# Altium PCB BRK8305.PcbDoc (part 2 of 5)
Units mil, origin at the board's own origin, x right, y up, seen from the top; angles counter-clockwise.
Board outline 5944.89 x 4139.76 mil, 4 copper layers (L1-Top, L2-GND, L3-GND, L4-BOT), stack 61.2 mil thick; 237 components, 286 nets, 1257 pads, 698 vias.
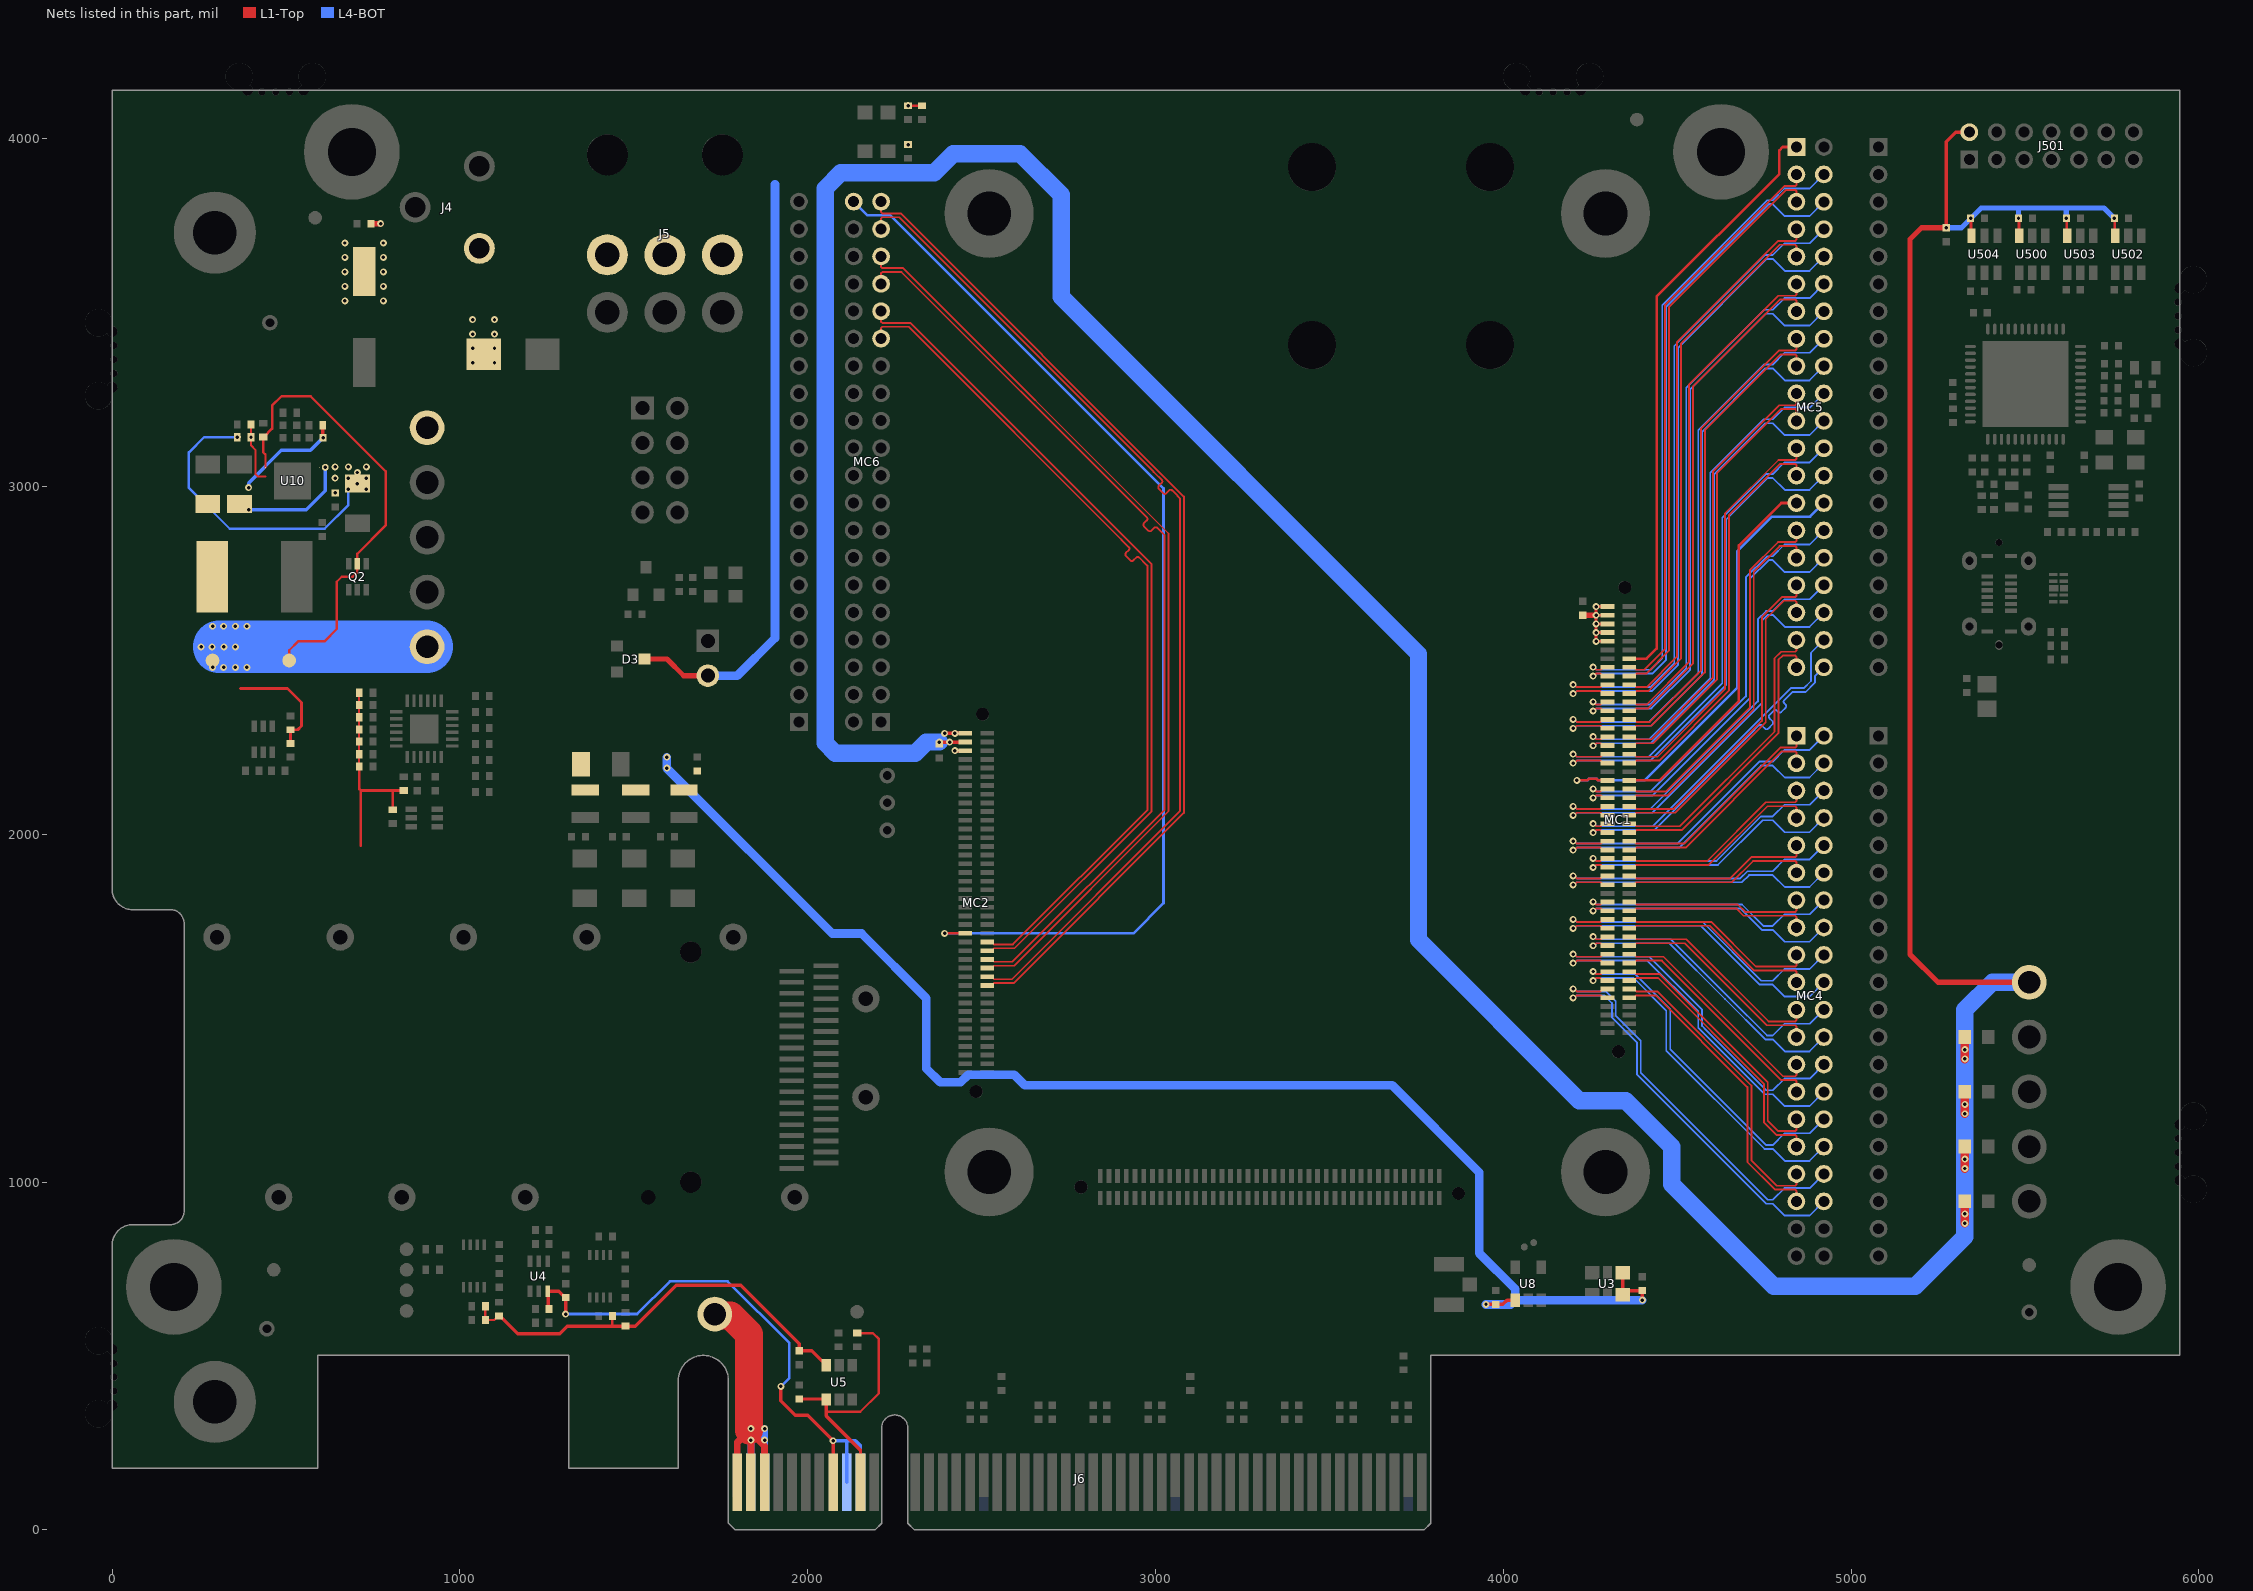
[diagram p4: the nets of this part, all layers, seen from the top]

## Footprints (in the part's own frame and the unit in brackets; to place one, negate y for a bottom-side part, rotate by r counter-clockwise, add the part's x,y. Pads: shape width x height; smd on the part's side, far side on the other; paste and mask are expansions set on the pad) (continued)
QSFP28_SINGLE_CAGE [mm]
  round 2 hole 1.05: 0(-1.1,3.1) 0(-1.1,-7.6) 0(-1.1,-16.6) 0(-1.1,-25.6) 0(-1.1,-34.6) 0(3.4,12.79) 0(10.6,12.79) 0(17.9,7.6) 0(17.9,-21.1) 0(17.9,-12.1) 0(17.9,-30.1)
  round 0 hole 1.05 unplated: 0(17.9,-3.1)
  L1-Top keep-out region: -2.7,13.5 -2.7,-37 19.5,-37 19.5,13.5 16.5,13.5 16.5,11.1 18,11.1 18,-1.6 15.9,-1.6 15.9,-3.5 0.9,-3.5 0.9,-1.6 -1.2,-1.6 -1.2,11.1 0.3,11.1 0.3,13.5
  silkscreen extent -1.1,-36.56 17.9,12.9, body extent -2,-48 18.81,12.91, height 10.41
RESC1005X06A [mm] "Chip Resistor, 2-Leads, Body 1.00x0.50mm, OK custom footprint"
  rect 0.5x0.6 smd mask+0.051: 1(-0.5,0) 2(0.5,0)
  body extent -0.52,-0.3 0.52,0.3, height 0.34
RESC1608N [mm] "Chip Resistor, Body 1.6x0.8mm, IPC Medium Density"
  rect 0.9x1 smd: 1(-0.85,0) 2(0.85,0)
  silkscreen extent -0.77,-0.68 0.78,0.68, body extent -0.84,-0.42 0.8,0.43, height 0.45
RESC2012N [mm] "Chip Resistor, Body 2.0x1.3mm, IPC Medium Density"
  rect 1.2x1.4 smd: 1(-0.9,0) 2(0.9,0)
  silkscreen extent -0.85,-0.89 0.85,0.88, body extent -1.07,-0.7 1.07,0.7, height 0.65
SIT9120AX-XB [mm]
  rect 1.05x1 smd: 1(-1.125,-0.8) 3(1.125,-0.8) 4(1.125,0.8) 6(-1.125,0.8)
  rect 0.65x1 smd: 2(0,-0.8) 5(0,0.8)
  silkscreen extent -1.85,-1.5 1.85,1.2
SOT23-5 [mm] "SOT-23; 5 Leads; Body 2.9 x 2.5 mm, inc. leads (LxW max)"
  rect 0.7x1 smd: 1(-0.95,-1.2) 2(0,-1.2) 3(0.95,-1.2) 4(0.95,1.2) 5(-0.95,1.2)
  silkscreen extent -1.5,-1.7 1.5,0.75
SOT23-6 [mm] "SOT-23; 6 Leads; Body 3.05 x 1.75 mm, inc. leads (LxW max)"
  rect 0.6x1.05 smd: 1(-0.95,-1.35) 2(0,-1.35) 3(0.95,-1.35) 4(0.95,1.35) 5(0,1.35) 6(-0.95,1.35)
  silkscreen extent -1.5,-1.9 1.5,0.75
SOT23-95P240X110 [mm] "SOT-23; 3 Leads; Body 3.0 x 2.6 mm, inc. leads (LxW max)"
  rect 0.8x0.9 smd: 1(-0.95,-1) 2(0.95,-1) 3(0,1)
  silkscreen extent -1.53,-1.45 1.54,0.77
SOT363-6N [mm] "SOT363, 6-Leads, Body 2x1.3mm, Pitch 0.65mm, Lead Span 2.1mm, IPC Medium Density"
  rect 0.85x0.4 smd: 1(-0.95,0.65) 2(-0.95,0) 3(-0.95,-0.65) 4(0.95,-0.65) 5(0.95,0) 6(0.95,0.65)
  silkscreen extent -1.37,-1.09 0.63,1.09, body extent -0.63,-1 0.63,1, height 1
Switch-PCB-wMounts [mm]
  round 3.5 hole 3.5 unplated paste-2539.97 mask+0.02: 0(-6.5,6.5) 0(-6.5,-6.5) 0(6.5,6.5) 0(6.5,-6.5)
  round 4.5 on Top Solder: 0(0,0)
  round 0.025 smd paste-1 mask-1: 1(-2.1,0) 2(2.1,0.001)
  L1-Top region: -0.672,-1.601 -0.664,-1.639 -0.642,-1.672 -0.61,-1.693 -0.572,-1.701 -0.572,-1.701 1.016,-1.701 0.657,-1.871 0.271,-1.967 0.271,-1.967 0.214,-1.982 0.17,-2.022 0.15,-2.077 0.159,-2.136 0.193,-2.183 0.246,-2.209 0.305,-2.208 0.305,-2.208 1.28,-1.829 1.97,-1.043 2.219,-0.027 2.219,-0.027 1.993,1.009 1.306,1.817 0.32,2.206 0.32,2.206 0.262,2.208 0.21,2.184 0.174,2.139 0.163,2.082 0.178,2.026 0.217,1.984 0.271,1.963 0.271,1.963 0.659,1.87 1.021,1.7 1.021,1.7 -0.6,1.7 -0.643,1.69 -0.678,1.662 -0.697,1.622 -0.697,1.578 -0.678,1.538 -0.643,1.51 -0.6,1.5 -0.6,1.5 1.297,1.5 1.561,1.222 1.767,0.899 1.767,0.899 -1.372,0.899 -1.415,0.889 -1.45,0.861 -1.469,0.821 -1.469,0.777 -1.45,0.737 -1.415,0.709 -1.372,0.699 -1.372,0.699 1.855,0.699 1.94,0.404 1.978,0.099 1.978,0.099 -1.572,0.099 -1.615,0.089 -1.65,0.061 -1.669,0.021 -1.669,-0.023 -1.65,-0.063 -1.615,-0.091 -1.572,-0.101 -1.572,-0.101 1.977,-0.101 1.937,-0.406 1.85,-0.701 1.85,-0.701 -1.472,-0.701 -1.515,-0.711 -1.55,-0.739 -1.569,-0.779 -1.569,-0.823 -1.55,-0.863 -1.515,-0.891 -1.472,-0.901 -1.472,-0.901 1.761,-0.901 1.555,-1.224 1.291,-1.501 1.291,-1.501 -0.572,-1.501 -0.61,-1.509 -0.642,-1.53 -0.664,-1.563 -0.672,-1.601
  L1-Top region: 1.213,-1.295 1.256,-1.285 1.291,-1.257 1.31,-1.217 1.31,-1.172 1.291,-1.132 1.256,-1.105 1.213,-1.095 1.213,-1.095 -1.648,-1.095 -1.806,-0.808 -1.915,-0.5 -1.915,-0.5 1.614,-0.5 1.657,-0.49 1.692,-0.462 1.711,-0.422 1.711,-0.378 1.692,-0.337 1.657,-0.31 1.614,-0.3 1.614,-0.3 -1.956,-0.3 -1.974,-0.153 -1.98,-0.005 -1.98,-0.005 -1.975,0.148 -1.958,0.301 -1.958,0.301 1.622,0.301 1.665,0.311 1.7,0.339 1.719,0.379 1.719,0.423 1.7,0.463 1.665,0.491 1.622,0.501 1.622,0.501 -1.917,0.501 -1.808,0.812 -1.649,1.1 -1.649,1.1 1.2,1.1 1.243,1.11 1.278,1.138 1.297,1.178 1.297,1.222 1.278,1.262 1.243,1.29 1.2,1.3 1.2,1.3 -1.497,1.3 -0.944,1.743 -0.271,1.963 -0.271,1.963 -0.217,1.984 -0.178,2.026 -0.163,2.082 -0.174,2.139 -0.21,2.184 -0.262,2.208 -0.32,2.206 -0.32,2.206 -1.306,1.817 -1.993,1.009 -2.219,-0.027 -2.219,-0.027 -1.97,-1.043 -1.28,-1.829 -0.305,-2.208 -0.305,-2.208 -0.246,-2.209 -0.193,-2.183 -0.159,-2.136 -0.15,-2.077 -0.17,-2.022 -0.214,-1.982 -0.271,-1.967 -0.271,-1.967 -0.944,-1.742 -1.497,-1.295 -1.497,-1.295
TP-PTH-25/45 [mil] "Test point, plated through-hole, 25/45mil"
  round 45 hole 25: 1(0,0)
TP-PTH-65/100 [mil] "Test point, plated through-hole, 65/100mil"
  round 100 hole 65: 1(0,0)
TP-SMD20 [mil] "Test point, surface-mount, 20mil"
  round 20 smd paste-78.74: 1(0,0)
TP-SMD40 [mm] "Test point, surface-mount, 40mil"
  round 1 smd paste-2: 1(0,0)
TPS54429E [mm]
  round 0.025 smd: 1(-1.975,0.975) 2(-1.975,0.325) 3(-1.975,-0.325) 4(-1.975,-0.975) 5(-0.975,-1.975) 6(-0.325,-1.975) 7(0.325,-1.975) 8(0.975,-1.975) 9(1.975,-0.975) 10(1.975,-0.325) 11(1.975,0.325) 12(1.975,0.975) 13(0.975,1.975) 14(0.325,1.975) 15(-0.325,1.975) 16(-0.975,1.975)
  rect 2.7x2.7 smd paste-10: PAD(0,0)
  L1-Top region: 1.15,2.4 1.15,1.725 1.137,1.658 1.099,1.601 1.042,1.563 0.975,1.55 0.975,1.55 0.908,1.563 0.851,1.601 0.813,1.658 0.8,1.725 0.8,1.725 0.8,2.4
  L1-Top region: 0.5,2.4 0.5,1.725 0.487,1.658 0.449,1.601 0.392,1.563 0.325,1.55 0.325,1.55 0.258,1.563 0.201,1.601 0.163,1.658 0.15,1.725 0.15,1.725 0.15,2.4
  L1-Top region: -0.15,2.4 -0.15,1.725 -0.163,1.658 -0.201,1.601 -0.258,1.563 -0.325,1.55 -0.325,1.55 -0.392,1.563 -0.449,1.601 -0.487,1.658 -0.5,1.725 -0.5,1.725 -0.5,2.4
  L1-Top region: -0.8,2.4 -0.8,1.725 -0.813,1.658 -0.851,1.601 -0.908,1.563 -0.975,1.55 -0.975,1.55 -1.042,1.563 -1.099,1.601 -1.137,1.658 -1.15,1.725 -1.15,1.725 -1.15,2.4
  L1-Top region: -1.15,-2.4 -1.15,-1.725 -1.137,-1.658 -1.099,-1.601 -1.042,-1.563 -0.975,-1.55 -0.975,-1.55 -0.908,-1.563 -0.851,-1.601 -0.813,-1.658 -0.8,-1.725 -0.8,-1.725 -0.8,-2.4
  L1-Top region: -0.5,-2.4 -0.5,-1.725 -0.487,-1.658 -0.449,-1.601 -0.392,-1.563 -0.325,-1.55 -0.325,-1.55 -0.258,-1.563 -0.201,-1.601 -0.163,-1.658 -0.15,-1.725 -0.15,-1.725 -0.15,-2.4
  L1-Top region: 0.8,-2.4 0.8,-1.725 0.813,-1.658 0.851,-1.601 0.908,-1.563 0.975,-1.55 0.975,-1.55 1.042,-1.563 1.099,-1.601 1.137,-1.658 1.15,-1.725 1.15,-1.725 1.15,-2.4
  L1-Top region: -2.4,0.5 -1.725,0.5 -1.658,0.487 -1.601,0.449 -1.563,0.392 -1.55,0.325 -1.55,0.325 -1.563,0.258 -1.601,0.201 -1.658,0.163 -1.725,0.15 -1.725,0.15 -2.4,0.15
  L1-Top region: -2.4,-0.15 -1.725,-0.15 -1.658,-0.163 -1.601,-0.201 -1.563,-0.258 -1.55,-0.325 -1.55,-0.325 -1.563,-0.392 -1.601,-0.449 -1.658,-0.487 -1.725,-0.5 -1.725,-0.5 -2.4,-0.5
  L1-Top region: -2.4,-0.8 -1.725,-0.8 -1.658,-0.813 -1.601,-0.851 -1.563,-0.908 -1.55,-0.975 -1.55,-0.975 -1.563,-1.042 -1.601,-1.099 -1.658,-1.137 -1.725,-1.15 -1.725,-1.15 -2.4,-1.15
  L1-Top region: 2.4,-1.15 1.725,-1.15 1.658,-1.137 1.601,-1.099 1.563,-1.042 1.55,-0.975 1.55,-0.975 1.563,-0.908 1.601,-0.851 1.658,-0.813 1.725,-0.8 1.725,-0.8 2.4,-0.8
  L1-Top region: 2.4,-0.5 1.725,-0.5 1.658,-0.487 1.601,-0.449 1.563,-0.392 1.55,-0.325 1.55,-0.325 1.563,-0.258 1.601,-0.201 1.658,-0.163 1.725,-0.15 1.725,-0.15 2.4,-0.15
  L1-Top region: 2.4,0.15 1.725,0.15 1.658,0.163 1.601,0.201 1.563,0.258 1.55,0.325 1.55,0.325 1.563,0.392 1.601,0.449 1.658,0.487 1.725,0.5 1.725,0.5 2.4,0.5
  L1-Top region: 2.4,0.8 1.725,0.8 1.658,0.813 1.601,0.851 1.563,0.908 1.55,0.975 1.55,0.975 1.563,1.042 1.601,1.099 1.658,1.137 1.725,1.15 1.725,1.15 2.4,1.15
  L1-Top region: 0.15,-2.4 0.15,-1.725 0.163,-1.658 0.201,-1.601 0.258,-1.563 0.325,-1.55 0.325,-1.55 0.392,-1.563 0.449,-1.601 0.487,-1.658 0.5,-1.725 0.5,-1.725 0.5,-2.4
  L1-Top region: -2.4,1.15 -1.725,1.15 -1.658,1.137 -1.601,1.099 -1.563,1.042 -1.55,0.975 -1.55,0.975 -1.563,0.908 -1.601,0.851 -1.658,0.813 -1.725,0.8 -1.725,0.8 -2.4,0.8
  L1-Top keep-out region: -2,1.5 -1.5,1.5 -1.5,2 -2,2
  silkscreen extent -2.35,-2.1 2.1,2.35
UFL-R-SMT-1 [mm] "U.FL surface-mount coaxial connector"
  rect 1x1.05 smd paste+0: 1(0,-1.525)
  rect 1.05x2.2 smd paste+0: 2(-1.475,0) 2(1.475,0)
  silkscreen extent -1.3,-1.3 1.3,1.3
USB4120-03-C [mm]
  rect 0.3x0.87 smd: A1(-2.75,0.865) A4(-1.25,0.865) A5(-0.75,0.865) A6(-0.25,0.865) A7(0.25,0.865) A8(0.75,0.865) A9(1.25,0.865) A12(2.75,0.865) B1(2.75,-0.865) B4(1.25,-0.865) B5(0.75,-0.865) B6(0.25,-0.865) B7(-0.25,-0.865) B8(-0.75,-0.865) B9(-1.25,-0.865) B12(-2.75,-0.865)
  oval 1.35x1.1 hole 0.6 slot 0.85 at 0 deg: M1(-2.4,2.15) M2(2.4,2.15) M3(2.4,-2.15) M4(-2.4,-2.15)
  round 0.52 hole 0.52 unplated paste-2539.97: M5(-3.75,0)
  oval 0.72x0.52 hole 0.52 slot 0.72 at 0 deg unplated paste-2539.97: M6(3.75,0)
  silkscreen extent -4.67,-1.8 4.67,1.8, body extent -4.47,-2.3 4.47,2.3, height 6.5
XILINX-JTAG [mm] "2mm 2x7 header"
  rect 1.3x1.3 hole 0.8: 1(-6,-1)
  round 1.3 hole 0.8: 2(-6,1) 3(-4,-1) 4(-4,1) 5(-2,-1) 6(-2,1) 7(0,-1) 8(0,1) 9(2,-1) 10(2,1) 11(4,-1) 12(4,1) 13(6,-1) 14(6,1)
  silkscreen extent -8.32,-3.15 8.32,3.15

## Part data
*: library part OKLOGO, partnumber=ALIGNI_IGNORE
C1 C3 C34: library part 000070, "Ceramic capacitor", Manufacturer=Kemet, Tolerance (%)=10, ValueFloat=1E-7
C2: library part 001983, "Ceramic capacitor", Manufacturer=Murata, Tolerance (%)=20, ValueFloat=1E-5
C5: library part 001532, "Polarized", Manufacturer=Panasonic, ValueFloat=0.00022, Voltage=25V, x_tolerance=20, x_voltage-rating=25
C6 C38: library part 001073, "Ceramic capacitor", Manufacturer="Taiyo Yuden", Tolerance (%)=10, ValueFloat=1E-7, Voltage=25V
C7 C8 C9 C10 C11 C12 C13 C14 C15 C16 C17 C18 C19 C20 C21 C22 C23 C24 C25 C26 C27 C28 C29 C30 C31 C32: library part 001073, Manufacturer=Kemet, partnumber=000070, ValueFloat=1E-7, x_tolerance=10
C33 C53: library part 000070, Manufacturer=Kemet, ValueFloat=1E-7, x_tolerance=10
C35 C36 C37 C90 C92 C95 C112 C522 C528: library part 000070, Manufacturer=Kemet, Manufacturer_PN=C0402C104K8PACTU, ValueFloat=1E-7, x_tolerance=10
C47: library part 001172, Manufacturer=TDK, ValueFloat=2.2E-5, Voltage=35V, x_tolerance=20, x_voltage-rating=35
C48: library part 001073, Manufacturer="Taiyo Yuden", ValueFloat=1E-7, Voltage=25V, x_tolerance=10
C49 C50: library part 001284, Manufacturer="Taiyo Yuden", ValueFloat=2.2E-5, Voltage=10V, x_tolerance=10
C54: library part 001297, Manufacturer=Kemet, ValueFloat=1E-11, x_tolerance=5, x_voltage-rating=50
C55: library part 001277, Manufacturer=Kemet, ValueFloat=3.3E-9, x_tolerance=10, x_voltage-rating=50
C56: library part 000480, Manufacturer="Taiyo Yuden", ValueFloat=1E-6, x_tolerance=10
C91 C93 C94 C111: library part 001284, Manufacturer="Taiyo Yuden", Manufacturer_PN=LMK316AB7226KL-TR, ValueFloat=2.2E-5, x_temperature_characteristic=X7R, x_tolerance=10
C500: library part 000824, Manufacturer="Taiyo Yuden", ValueFloat=4.7E-6, x_tolerance=20
C501 C505 C511 C513: library part 000824, "Ceramic capacitor", Manufacturer="Taiyo Yuden", Tolerance (%)=20, ValueFloat=4.7E-6
C502 C503 C504 C506 C507 C508 C509 C512 C514 C515 C516 C517 C518 C519 C520 C525 C526 C527: library part 000070, Manufacturer=Kemet, Tolerance (%)=10, ValueFloat=1E-7
C510 C521: library part 000295, "Ceramic Capacitor", Manufacturer=Kemet, Tolerance (%)=10, ValueFloat=1E-8
C523 C524: library part 001640, "Ceramic capacitor", Manufacturer=Kemet, Tolerance (%)=5, ValueFloat=1.8E-11, Voltage=50
D1 D2: library part 001433, "LED", Manufacturer=Dialight, Manufacturer_PN=598-8070-107F
D3: library part 002130, "High Conductance, Ultra Fast Diode", Manufacturer="Micro Commercial Co"
D4: library part 002129, "Transient Voltage Suppressor", Manufacturer="Diodes Incorporated", Manufacturer_PN=SMBJ15CA-13-F, Voltage=15V
D500: library part 002405, "4 channel TVS diode array", Manufacturer="Diodes Incorporated"
FB500 FB501 FB502: library part 000569, "Ferrite bead", Manufacturer=Steward, ValueFloat=600
FB503: library part 000783, "Ferrite Chip", Manufacturer=Murata, ValueFloat=220
FID1 FID2 FID3 FID4: "PCB fiducial"
J1: library part 001335, "U.FL surface-mount coaxial connector", Manufacturer=Hirose, Manufacturer_PN=U.FL-R-SMT-1
J2: library part 001193, Manufacturer="Sullins Electronics Corp."
J3: library part 002124, Manufacturer=Molex
J4: library part 000356, "DC power connector - high current", Manufacturer="CUI Inc."
J5: library part 001950, Manufacturer=Molex
J6: library part PCIEX8
J30: library part 001782, Manufacturer=Amphenol
J500: library part 002404, "USB 2.0 Type-C receptacle vertical-mount", Manufacturer=GCT
J501: library part 000541, "2mm header, shrouded", Manufacturer=Molex
L5 L6 L7: library part 002331, "Thin Film, 1uH, 3.1A, 50mOhm, Unshielded", Manufacturer="Samsung Electro-Mechanics", Tolerance (%)=20, ValueFloat=1E-6
L14: library part 002116, Manufacturer=Murata, Manufacturer_PN=1267AY-3R3N{}P3, ValueFloat=3.3E-6, x_tolerance=30
MB1 MB2 MB3 MB4 MB5 MB6: library part MouseBite
MC1: library part 002562, "0.635mm hi-speed, high-density socket (female)", Manufacturer=Samtec
MC2 MC3: library part 002561, "0.635mm hi-speed, high-density socket (female)", Manufacturer=Samtec
MC4 MC5 MC6: library part 000583, Manufacturer=Molex
MC7 MC8 MC9: library part 001334, Manufacturer=3M, Manufacturer_PN=951120-8622-AR
MH1 MH2 MH3 MH4: "Mounting hole"
Q1 Q2 Q3: library part 002018, Manufacturer=Vishay
QSFP: library part 001781, Manufacturer=Amphenol, Manufacturer_PN=U95-T111-1001
R1 R18 R24 R25 R32 R33 R507 R508: library part 001070, "Thick-film resistor", Manufacturer=Vishay, Tolerance (%)=1, ValueFloat=100000
R3 R4 R509: library part 001162, "Thick-film resistor", Manufacturer=Vishay, Tolerance (%)=1, ValueFloat=2000
R5 R6 R19 R34 R35 R36: library part 000411, "Zero-ohm resistor", Manufacturer=Vishay, ValueFloat=0
R12 R16 R17 R20 R21 R22 R26: library part Resistor-NoLoad, "Resistor, NoLoad", partnumber=ALIGNI_IGNORE
R13 R23: library part 000964, Manufacturer=Vishay, ValueFloat=200000, x_tolerance=1
R14 R15 R30 R31 R39 R40 R41 R42 R43 R44 R45 R46 R47 R48 R49 R80 R81 R82: library part 001008, Manufacturer=Vishay, ValueFloat=4750, x_tolerance=1
R27 R28 R29 R76: library part 000755, Manufacturer=Vishay, ValueFloat=0, x_tolerance=1
R37 R503 R510: library part 001521, "Thick-film resistor", Manufacturer=Vishay, Tolerance (%)=1, ValueFloat=10000
R38: library part 000964, "Thick-film resistor", Manufacturer=Vishay, Tolerance (%)=1, ValueFloat=200000
R75 R79: library part 001521, Manufacturer=Vishay, ValueFloat=10000, x_tolerance=1
R77: library part 002123, Manufacturer=Vishay, ValueFloat=73200, x_tolerance=1
R78: library part 002121, Manufacturer=Vishay, ValueFloat=22100, x_tolerance=1
R500 R501: library part 001919, "Thick-film resistor", Manufacturer=Vishay, Tolerance (%)=1, ValueFloat=5100
R502: library part 000826, "Thick-film resistor", Manufacturer=Vishay, Tolerance (%)=1, ValueFloat=12000
R504 R505 R506: library part 000755, "Thick-film resistor", Manufacturer=Vishay, Tolerance (%)=1, ValueFloat=0
S1: "Pushbutton", Manufacturer="Generic Components"
TP1 TP2 TP17 TP27 TP28 TP29: library part TP-PTH-25/45, "Test point, plated through-hole, 25/45mil"
TP3 TP4 TP6 TP8 TP18 TP22 TP23 TP24 TP25 TP26: library part TP-PTH-65/100, "Test point, plated through-hole, 65/100mil", partnumber=ALIGNI_IGNORE
TP9 TP12 TP13 TP15 TP19 TP21 TP32: library part TESTPOINT-SMD40, "Test point, surface-mount, 40mil"
TP20: library part TP-PTH-65/100, "Test point, plated through-hole, 65/100mil"
TP30 TP31: "Test point, surface-mount, 20mil", partnumber=ALIGNI_IGNORE
U1: library part 000728, "1.25V Voltage Reference", Manufacturer="Texas Instruments"
U2 U6: library part 001474, Manufacturer="Texas Instruments"
U3: library part 002434, Manufacturer=SiTime
U4: library part 002140, "Level Translator, 0.65V - 3.6V, Direction Control", Manufacturer="Texas Instruments"
U5: library part 002224, "Load Switch with Adjustable Current Limit, Latching", Manufacturer="Diodes Incorporated"
U7: library part 002527, Manufacturer=NXP
U8: library part 002537, Manufacturer="ON Semiconductor"
U10: library part 002118, "Step-down converter, 4.5 A, 7-18V input, 0.76-5.5V output, 4x4 mm", Manufacturer="Texas Instruments"
U500 U502 U503 U504: library part 002400, "Level Translator, 0.65V - 3.6V, Direction Control", Manufacturer="Texas Instruments"
U501: library part 002398, Manufacturer=FTDI
U505: library part 002441, Manufacturer="Opal Kelly Incorporated"
Y500: library part 002402, "Crystal", Manufacturer=Abracon

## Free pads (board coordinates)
  round 275.59 hole 137.8: MH(177.17,698.82) MH(688.98,3962.6) MH(4625.98,3962.6) MH(5767.71,698.82)
  round 236.22 hole 125.2: PCIE_MOUNT(295.27,368.11) PCIE_MOUNT(295.27,3730.31)
  round 20 hole 10 mask+2: ViaNoConnect1(606.23,3140.61) ViaNoConnect1(612.67,3055.31)

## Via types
v1: diameter 20, hole 10, L1-Top to L4-BOT, tented both sides, 698 vias

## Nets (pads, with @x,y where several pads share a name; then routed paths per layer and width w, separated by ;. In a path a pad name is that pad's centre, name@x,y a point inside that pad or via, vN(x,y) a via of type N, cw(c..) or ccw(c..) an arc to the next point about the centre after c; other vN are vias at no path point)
+1.8V: C34.2 C504.2 C516.2 C520.2 C526.2 C528.2 J501.2 MC2.75 MC2.77 MC2.79 R19.1 R34.1 R35.1 R36.1 TP6.1 U500.6 U502.6 U503.6 U504.6 | length 12330
  L1-Top w8: v1(5343.26,3770.87) 5344.44,3769.69 5344.44,3722.84 U504.6@5345.62,3721.66 ; v1(5481.05,3770.87) 5482.24,3769.69 5482.24,3722.84 U500.6@5483.42,3721.66 ; v1(5618.85,3770.87) 5620.03,3769.69 5620.03,3722.84 U503.6@5621.21,3721.66 ; v1(5756.64,3770.87) 5757.83,3769.69 5757.83,3722.84 U502.6@5759.01,3721.66
  L1-Top w10: v1(2378.07,2265.55) v1(2407.6,2265.55) MC2.77@2452.76,2265.55 ; v1(2393.7,2290.55) v1(2423.23,2290.55) MC2.79@2452.76,2290.55 ; v1(2423.23,2240.55) MC2.75@2452.76,2240.55 ; v1(5272.79,3744.1) 5272.79,3991.34 5300.35,4018.9 J501.2@5339.72,4018.9
  L1-Top w15: v1(5272.79,3744.1) 5202.37,3744.1 5169.29,3711.02 5169.29,1655.11 5249.6,1574.8 TP6.1@5511.81,1574.8
  L1-Top w25: v1(5326.77,881.89) v1(5326.77,908.96) R36.1@5326.77,944.88 ; v1(5326.77,1039.37) v1(5326.77,1066.44) R35.1@5326.77,1102.36 ; v1(5326.77,1196.85) v1(5326.77,1223.92) R34.1@5326.77,1259.84 ; v1(5326.77,1354.33) v1(5326.77,1381.4) R19.1@5326.77,1417.32
  L4-BOT w15: v1(5272.79,3744.1) 5317.27,3744.1 5373.98,3800.8 5481.05,3800.8 ; v1(5481.05,3770.87) 5481.05,3800.8 ; v1@5618.46,3770.87 5618.46,3800.8 ; v1(5756.64,3770.87) 5726.71,3800.8 5618.46,3800.8 ; 5481.05,3800.8 5618.46,3800.8
  L4-BOT w50: v1(2378.07,2265.55) 2340.77,2265.55 2308.72,2233.51 2079.2,2233.51 2049.91,2262.8 2049.91,3857.01 2095.06,3902.16 2363.4,3902.16 2417.93,3956.69 2610.24,3956.69 2728.35,3838.58 2728.35,3546.26 3755.91,2518.7 3755.91,1696.85 4218.5,1234.25 4352.36,1234.25 4484.25,1102.36 4484.25,994.14 4777.61,700.79 5184.71,700.79 5326.77,842.85 v1(5326.77,881.89) v1(5326.77,908.96) v1(5326.77,1039.37) v1(5326.77,1066.44) v1(5326.77,1196.85) v1(5326.77,1223.92) v1(5326.77,1354.33) v1(5326.77,1381.4) 5326.77,1495.36 5406.22,1574.8 TP6.1@5511.81,1574.8
+3.3V: C33.2 C37.2 C49.2 C50.2 C54.2 C111.2 C112.2 L5.1 L6.1 L7.1 L14.2 pad.ViaNoConnect1 R30.2 R31.2 R37.2 R38.2 R42.2 R43.2 R46.2 R47.2 R77.2 R80.2 R81.2 R82.2 TP3.1 TP19.1 U3.1 U3.6 U8.1 U10.16 | length 6270.5
  L1-Top w6: R42.2@710.24,2194.88 R46.2@710.24,2230.32 R80.2@710.24,2266.78 R47.2@710.24,2301.18 R43.2@710.24,2336.61 R82.2@710.24,2372.05 R81.2@710.24,2407.48
  L1-Top w8: 369.33,2419.29 504.28,2419.29 544.08,2379.5 544.08,2311.26 533.67,2300.85 R30.2@512.89,2300.85 R31.2@512.89,2261.48 ; R42.2@710.24,2194.88 710.24,2130.87 714.92,2126.18 ; 714.92,1968.46 714.92,2126.18 ; R37.2@806.69,2070.87 806.69,2125.3 805.81,2126.18 ; R38.2@838.39,2126.18 805.81,2126.18 ; 714.92,2126.18 805.81,2126.18
  L1-Top w10: R77.2@605.44,3176.22 605.84,3175.82 605.84,3141.01 pad.ViaNoConnect1@606.23,3140.61 ; v1(3950,648.61) 3950.2,648.8 C37.2@3977.36,648.8 ; C37.2@3977.56,648.61 3998.01,648.61 4010.35,660.95 U8.1@4034.51,660.95 ; U3.1@4343.56,739.69 U3.6@4343.56,676.69 4354.98,688.11 C33.2@4399.38,688.11 v1(4399.38,660.95)
  L4-BOT w10: v1(392.15,2933.61) 558.15,2933.61 612.47,2987.93 pad.ViaNoConnect1@612.47,3055.5 ; v1(392.15,2997.27) 392.15,3010.35 486.42,3104.61 570.23,3104.61 pad.ViaNoConnect1@606.23,3140.61
  L4-BOT w25: v1(1594.85,2222.14) v1(1594.85,2190.35) 2070.36,1714.84 2154.7,1714.84 2340.77,1528.76 2340.77,1327.12 2380.84,1287.05 2439.37,1287.05 2461.45,1309.13 2593.31,1309.13 2623.41,1279.04 3680.06,1279.04 3931,1028.09 3931,795.57 4033.69,692.89 4033.69,660.95 ; v1(3950,648.61) 4021.35,648.61 4033.69,660.95 ; v1(4399.38,660.95) 4033.69,660.95
  L4-BOT w150: 307.09,2539.37 v1(321.01,2539.37) v1(354.33,2539.37) TP3.1@905.51,2539.37
  other v1: 288.48,2480.32 320.42,2480.32 354.02,2480.32 387.35,2480.32 255.47,2539.37 287.4,2539.37 288.48,2598.43 320.42,2598.43 354.02,2598.43 387.35,2598.43
+3.3V_EN: R75.1 R76.1 U10.6 | length 180
  L1-Top w6: R76.1@398.85,3178.78 398.85,3142.23 v1(399.15,3141.93) 399.15,3118.49 412.62,3105.02 412.62,3035.14 418.32,3029.45 U10.6@440.91,3029.45
+3.3V_PCIE_C: C12.2 J6.A9 J6.A10 J6.B8 R21.2 U4.6 | length 1716.3
  L1-Top w10: R21.2@1256.19,635.26 1254.14,637.31 1254.14,684.55 U4.6@1252.25,686.44 1284.34,686.44 1302.84,667.94 C12.2@1303.43,667.94 v1(1303.43,620.68) ; v1(1922.6,413.07) 1922.6,371.12 1964.31,329.42 2000,329.42 v1(2072.83,256.59) J6.B8@2072.83,137.79
  L4-BOT w8: v1(1303.43,620.68) 1509.43,620.68 1603.71,714.96 1769.05,714.96 1946.89,537.12 1946.89,437.36 v1(1922.6,413.07)
  L4-BOT w10: v1(2072.83,256.59) 2114.17,256.59 ; J6.A9@2112.2,137.79 2112.2,254.61 2114.17,256.59 ; J6.A10@2151.57,137.79 2151.57,242.13 2137.11,256.59 2114.17,256.59
+3.3V_PG: Q2.2 R79.1 TP32.1 U10.5 | length 1341
  L1-Top w7: U10.5@440.91,3055.04 440.91,3091.86 434.15,3098.61 R79.1@434.15,3142.93 436.12,3142.93 459.91,3166.72 459.91,3232.96 486.79,3259.84 570.36,3259.84 786.2,3044 786.2,2888.09 705.15,2807.04 705.15,2754.3 691.46,2740.6 659.92,2740.6 645.67,2726.35 645.67,2590.55 610.24,2555.12 534.55,2555.12 508.96,2529.53 TP32.1@508.96,2500
+3.3VAUX_PCIE: C31.2 R13.2 R16.2 R17.2 R23.2 R26.2 U5.6 | length 1243
  L1-Top w7: R16.2@1073.12,643.14 R17.2@1073.12,603.77 1098.71,603.77 1110.52,615.58 R13.2@1112.49,615.58 ; 1438.27,586.05 R26.2@1438.27,615.58
  L1-Top w10: R13.2@1112.49,615.58 1114.45,615.58 1166.22,563.82 1286.58,563.82 1308.82,586.05 1438.27,586.05 R23.2@1475.67,586.05 1503.37,586.05 1621.48,704.16 1806.74,704.16 1975.47,535.43 C31.2@1975.47,515.24 2011.53,515.24 2040.43,486.34 2044.36,486.34 2053.14,477.56 U5.6@2053.14,473.62
+3.3VAUX_PCIE_C: C32.2 J6.B10 R18.2 U5.1 | length 754.3
  L1-Top w7: 2053.14,339.98 2150.99,339.98 2204.34,393.33 2204.34,548.63 2186.83,566.14 R18.2@2142.43,566.14
  L1-Top w8: C32.2@1975.47,376.92 2051.42,376.92 U5.1@2053.14,375.2
  L1-Top w10: U5.1@2053.14,375.2 2053.14,339.98 2053.14,327.85 2151.57,229.43 J6.B10@2151.57,137.79
+12V_PCIE_C: J6.A2 J6.A3 J6.B1 J6.B2 J6.B3 TP20.1 | length 1178.2
  L1-Top w20: J6.B1@1797.24,137.79 1797.24,252.07 1831.02,285.86 1836.61,280.27 ; J6.B2@1836.61,137.79 v1(1836.61,258.56) 1836.61,280.27 ; J6.B3@1875.98,137.79 1875.98,240.9 1836.61,280.27
  L1-Top w80: TP20.1@1732.73,620.68 1736.56,616.85 1777.99,616.85 1831.02,563.82 v1@1831.02,285.86
  L4-BOT w20: J6.A2@1836.61,137.79 v1(1836.61,258.56) v1(1836.61,291.39) ; J6.A3@1875.98,137.79 v1(1875.98,258.56) v1(1875.98,291.39)
+VDCIN: C5.1 C6.2 C38.2 C47.2 C48.2 D3.3 D4.2 J3.2 J4.1 J5.1 J5.2 J5.3 MC1.91 MC1.93 MC1.95 MC1.97 MC1.99 R1.2 R3.2 R4.2 R75.2 TP4.1 U10.13 U10.14 U10.15 | length 2953
  L1-Top w8: v1(2288.34,4095.15) R1.2@2328.64,4095.15 ; v1(4266.46,2555.1) v1(4266.46,2580.1) v1(4266.46,2605.1) v1(4266.46,2630.1) v1(4266.46,2655.1) ; v1@4266.66,2555.3 MC1.91@4299.21,2555.3 ; v1@4266.66,2580.3 MC1.93@4299.21,2580.3 ; v1@4266.66,2605.3 MC1.95@4299.21,2605.3 ; v1@4266.66,2630.3 MC1.97@4299.21,2630.3 ; v1@4266.66,2655.3 MC1.99@4299.21,2655.3
  L1-Top w15: C6.2@744.88,3755.91 v1(772.05,3755.91) ; D3.3@1530.44,2504.01 1595.44,2504.01 1643.16,2456.3 J3.2@1712.55,2456.3 ; C38.2@4228.45,2630.1 v1(4266.46,2630.1)
  L4-BOT w7: v1(359.78,3141.93) 263.97,3141.93 220.47,3098.43 220.47,2996.21 338.07,2878.61 610.61,2878.61 679.15,2947.15 v1(679.15,2992.79)
  L4-BOT w25: J3.2@1712.55,2456.3 1797.09,2456.3 1905.51,2564.72 1905.51,3868.83
  other v1: 641.15,2981.69 731.15,2992.79 705.15,3008.7 641.15,3024.61 679.15,3024.61 731.15,3024.61 705.15,3040.53 641.15,3056.44 679.15,3056.44 731.15,3056.44 1036.22,3355.55 1099.21,3355.55 1036.22,3397.08 1099.21,3397.08 1036.22,3438.61 1099.21,3438.61 1036.22,3480.14 1099.21,3480.14 669.16,3534.26 779.76,3534.26 669.16,3575.79 779.76,3575.79 669.16,3617.32 779.76,3617.32 669.16,3658.85 779.76,3658.85 669.16,3700.38 779.76,3700.38 2288.34,3983.49
B64_L1N: MC1.86 MC5.3 | length 1670
  L1-Top w5.25: MC1.86@4362.2,2480.3 4375,2480.3 4381.87,2473.43 4405.51,2473.43 4464.54,2532.46 4464.54,3520.79 4807.65,3863.89 4839.44,3863.89 4842.52,3866.97 MC5.3@4842.52,3897.64
B64_L1P: MC1.84 MC5.5 | length 1670
  L1-Top w5.25: MC1.84@4362.2,2455.3 4375,2455.3 4381.87,2462.18 4410.17,2462.18 4475.79,2527.8 4475.79,3516.13 4812.31,3852.64 4839.44,3852.64 4842.52,3849.57 MC5.5@4842.52,3818.9
B64_L2N: MC1.82 MC5.7 | length 1576.7
  L1-Top w5.25: MC1.82@4362.2,2430.3 4375,2430.3 4381.87,2423.43 4412.22,2423.43 4499.04,2510.26 4499.04,3415.33 4790.12,3706.41 4839.44,3706.41 4842.52,3709.49 MC5.7@4842.52,3740.16
B64_L2P: MC1.80 MC5.9 | length 1576.7
  L1-Top w5.25: MC1.80@4362.2,2405.3 4375,2405.3 4381.87,2412.18 4416.88,2412.18 4510.29,2505.6 4510.29,3410.67 4794.78,3695.16 4839.44,3695.16 4842.52,3692.09 MC5.9@4842.52,3661.42
B64_L3N: MC1.78 MC5.11 | length 1469.1
  L1-Top w5.25: MC1.78@4362.2,2380.3 4375,2380.3 4381.87,2373.43 4411.91,2373.43 4533.54,2495.07 4533.54,3292.34 4790.13,3548.93 4839.44,3548.93 4842.52,3552.01 MC5.11@4842.52,3582.68
B64_L3P: MC1.76 MC5.13 | length 1469.1
  L1-Top w5.25: MC1.76@4362.2,2355.3 4375,2355.3 4381.87,2362.18 4416.57,2362.18 4544.79,2490.41 4544.79,3287.68 4794.79,3537.68 4839.44,3537.68 4842.52,3534.61 MC5.13@4842.52,3503.94
B64_L4N: MC1.74 MC5.15 | length 1364.9
  L1-Top w5.25: MC1.74@4362.2,2330.3 4375,2330.3 4381.87,2323.43 4420.97,2323.43 4568.04,2470.5 4568.04,3166.06 4793.44,3391.45 4839.44,3391.45 4842.52,3394.53 MC5.15@4842.52,3425.2
B64_L4P: MC1.72 MC5.17 | length 1364.9
  L1-Top w5.25: MC1.72@4362.2,2305.3 4375,2305.3 4381.87,2312.18 4425.63,2312.18 4579.29,2465.84 4579.29,3161.4 4798.1,3380.2 4839.44,3380.2 4842.52,3377.13 MC5.17@4842.52,3346.46
B64_L5N: MC1.70 MC5.19 | length 1260.6
  L1-Top w5.25: MC1.70@4362.2,2280.3 4375,2280.3 4381.87,2273.43 4426.17,2273.43 4602.54,2449.8 4602.54,3043.28 4793.24,3233.97 4839.44,3233.97 4842.52,3237.05 MC5.19@4842.52,3267.72
B64_L5P: MC1.68 MC5.21 | length 1260.6
  L1-Top w5.25: MC1.68@4362.2,2255.3 4375,2255.3 4381.87,2262.18 4430.83,2262.18 4613.79,2445.14 4613.79,3038.62 4797.9,3222.72 4839.44,3222.72 4842.52,3219.65 MC5.21@4842.52,3188.98
B64_L6N: MC1.66 MC5.23 | length 1164.4
  L1-Top w5.25: MC1.66@4362.2,2230.3 4375,2230.3 4381.87,2223.43 4443.06,2223.43 4637.04,2417.41 4637.04,2922.59 4790.95,3076.49 4839.44,3076.49 4842.52,3079.57 MC5.23@4842.52,3110.24
B64_L6P: MC1.64 MC5.25 | length 1164.4
  L1-Top w5.25: MC1.64@4362.2,2205.3 4375,2205.3 4381.87,2212.18 4447.72,2212.18 4648.29,2412.75 4648.29,2917.93 4795.61,3065.24 4839.44,3065.24 4842.52,3062.17 MC5.25@4842.52,3031.5
B64_L7N: MC1.85 MC5.4 | length 1898.1
  L1-Top w5.25: v1(4257.87,2480.8) 4259.32,2480.8 4266.7,2473.43 4279.54,2473.43 4286.42,2480.3 MC1.85@4299.21,2480.3
  L4-BOT w5.25: v1(4257.87,2480.8) 4260.95,2480.8 4268.32,2473.43 4423.43,2473.43 4456.61,2506.61 4456.61,3521.54 4758.45,3823.37 4774.55,3823.37 4808.27,3857.1 4880.72,3857.1 MC5.4@4921.26,3897.64
B64_L7P: MC1.83 MC5.6 | length 1898.6
  L1-Top w5.25: v1(4257.87,2454.8) 4259.32,2454.8 4266.7,2462.18 4279.54,2462.18 4286.42,2455.3 MC1.83@4299.21,2455.3
  L4-BOT w5.25: v1(4257.87,2454.8) 4260.95,2454.8 4268.32,2462.18 4428.09,2462.18 4467.86,2501.95 4467.86,3516.88 4763.11,3812.12 4774.49,3812.12 4808.82,3777.8 4880.16,3777.8 MC5.6@4921.26,3818.9
B64_L8N: MC1.81 MC5.8 | length 1907.4
  L1-Top w5.25: v1(4200.79,2430.8) 4203.86,2430.8 4211.24,2423.43 4279.54,2423.43 4286.42,2430.3 MC1.81@4299.21,2430.3
  L4-BOT w5.25: v1(4200.79,2430.8) 4203.86,2430.8 4211.24,2423.43 4422.22,2423.43 4491.11,2492.32 4491.11,3404.14 4752.87,3665.89 4774.55,3665.89 4808.27,3699.62 4880.72,3699.62 MC5.8@4921.26,3740.16
B64_L8P: MC1.79 MC5.10 | length 1907.9
  L1-Top w5.25: v1(4200.79,2404.8) 4203.86,2404.8 4211.24,2412.18 4279.54,2412.18 4286.42,2405.3 MC1.79@4299.21,2405.3
  L4-BOT w5.25: v1(4200.79,2404.8) 4203.86,2404.8 4211.24,2412.18 4426.88,2412.18 4502.36,2487.66 4502.36,3399.48 4757.53,3654.64 4774.49,3654.64 4808.82,3620.32 4880.16,3620.32 MC5.10@4921.26,3661.42
B64_L9N: MC1.77 MC5.12 | length 1686.7
  L1-Top w5.25: v1(4257.87,2380.8) 4259.32,2380.8 4266.7,2373.43 4279.54,2373.43 4286.42,2380.3 MC1.77@4299.21,2380.3
  L4-BOT w5.25: v1(4257.87,2380.8) 4260.95,2380.8 4268.32,2373.43 4421.01,2373.43 4525.61,2478.03 4525.61,3283.98 4750.05,3508.41 4774.55,3508.41 4808.27,3542.14 4880.72,3542.14 MC5.12@4921.26,3582.68
B64_L9P: MC1.75 MC5.14 | length 1687.2
  L1-Top w5.25: v1(4257.87,2354.8) 4259.32,2354.8 4266.7,2362.18 4279.54,2362.18 4286.42,2355.3 MC1.75@4299.21,2355.3
  L4-BOT w5.25: v1(4257.87,2354.8) 4260.95,2354.8 4268.32,2362.18 4425.67,2362.18 4536.86,2473.37 4536.86,3279.32 4754.71,3497.16 4774.49,3497.16 4808.82,3462.84 4880.16,3462.84 MC5.14@4921.26,3503.94
B64_L10N: MC1.73 MC5.16 | length 1693.5
  L1-Top w5.25: v1(4200.79,2330.8) 4203.86,2330.8 4211.24,2323.43 4279.54,2323.43 4286.42,2330.3 MC1.73@4299.21,2330.3
  L4-BOT w5.25: v1(4200.79,2330.8) 4203.86,2330.8 4211.24,2323.43 4419.8,2323.43 4560.11,2463.74 4560.11,3162.47 4748.58,3350.93 4774.55,3350.93 4808.27,3384.66 4880.72,3384.66 MC5.16@4921.26,3425.2
B64_L10P: MC1.71 MC5.18 | length 1694
  L1-Top w5.25: v1(4200.79,2304.8) 4203.86,2304.8 4211.24,2312.18 4279.54,2312.18 4286.42,2305.3 MC1.71@4299.21,2305.3
  L4-BOT w5.25: v1(4200.79,2304.8) 4203.86,2304.8 4211.24,2312.18 4424.46,2312.18 4571.36,2459.08 4571.36,3157.81 4753.24,3339.68 4774.49,3339.68 4808.82,3305.36 4880.16,3305.36 MC5.18@4921.26,3346.46
B64_L11N_GC: MC1.69 MC5.20 | length 1471.2
  L1-Top w5.25: v1(4257.87,2280.8) 4259.32,2280.8 4266.7,2273.43 4279.54,2273.43 4286.42,2280.3 MC1.69@4299.21,2280.3
  L4-BOT w5.25: v1(4257.87,2280.8) 4260.95,2280.8 4268.32,2273.43 4418.59,2273.43 4594.61,2449.45 4594.61,3039.57 4748.49,3193.45 4774.55,3193.45 4808.27,3227.18 4880.72,3227.18 MC5.20@4921.26,3267.72
B64_L11P_GC: MC1.67 MC5.22 | length 1471.7
  L1-Top w5.25: v1(4257.87,2254.8) 4259.32,2254.8 4266.7,2262.18 4279.54,2262.18 4286.42,2255.3 MC1.67@4299.21,2255.3
  L4-BOT w5.25: v1(4257.87,2254.8) 4260.95,2254.8 4268.32,2262.18 4423.25,2262.18 4605.86,2444.79 4605.86,3034.91 4753.15,3182.2 4774.49,3182.2 4808.82,3147.88 4880.16,3147.88 MC5.22@4921.26,3188.98
B64_L12N_GC: MC1.65 MC5.24 | length 1473.4
  L1-Top w5.25: v1(4200.79,2230.8) 4203.86,2230.8 4211.24,2223.43 4279.54,2223.43 4286.42,2230.3 MC1.65@4299.21,2230.3
  L4-BOT w5.25: v1(4200.79,2230.8) 4203.86,2230.8 4211.24,2223.43 4417.38,2223.43 4629.11,2435.16 4629.11,2910.05 4755.04,3035.97 4774.55,3035.97 4808.27,3069.7 4880.72,3069.7 MC5.24@4921.26,3110.24
B64_L12P_GC: MC1.63 MC5.26 | length 1473.8
  L1-Top w5.25: v1(4200.79,2204.8) 4203.86,2204.8 4211.24,2212.18 4279.54,2212.18 4286.42,2205.3 MC1.63@4299.21,2205.3
  L4-BOT w5.25: v1(4200.79,2204.8) 4203.86,2204.8 4211.24,2212.18 4422.04,2212.18 4640.36,2430.5 4640.36,2905.39 4759.7,3024.72 4774.49,3024.72 4808.82,2990.4 4880.16,2990.4 MC5.26@4921.26,3031.5
B64_L13N_GC: MC1.58 MC5.29 | length 1043.6
  L1-Top w5.25: MC1.58@4362.2,2130.3 4375,2130.3 4381.87,2123.43 4468.06,2123.43 4708.64,2364.01 4708.64,2759.37 4789.54,2840.27 4839.44,2840.27 4842.52,2843.35 MC5.29@4842.52,2874.02
B64_L13P_GC: MC1.56 MC5.31 | length 1043.6
  L1-Top w5.25: MC1.56@4362.2,2105.3 4375,2105.3 4381.87,2112.18 4472.72,2112.18 4719.89,2359.35 4719.89,2754.71 4794.2,2829.02 4839.44,2829.02 4842.52,2825.95 MC5.31@4842.52,2795.28
B64_L14N_GC: MC1.54 MC5.33 | length 941.8
  L1-Top w5.25: MC1.54@4362.2,2080.3 4375,2080.3 4381.87,2073.43 4490.09,2073.43 4743.14,2326.48 4743.14,2623.99 4801.94,2682.79 4839.44,2682.79 4842.52,2685.87 MC5.33@4842.52,2716.54
B64_L14P_GC: MC1.52 MC5.35 | length 941.8
  L1-Top w5.25: MC1.52@4362.2,2055.3 4375,2055.3 4381.87,2062.18 4494.75,2062.18 4754.39,2321.82 4754.39,2619.33 4806.6,2671.54 4839.44,2671.54 4842.52,2668.47 MC5.35@4842.52,2637.8
B64_L15N: MC1.50 MC5.37 | length 846.7
  L1-Top w5.25: MC1.50@4362.2,2030.3 4375,2030.3 4381.87,2023.43 4507.68,2023.43 4779.53,2295.28 4779.53,2506.46 4798.38,2525.31 4839.44,2525.31 4842.52,2528.39 MC5.37@4842.52,2559.06
B64_L15P: MC1.48 MC5.39 | length 846.7
  L1-Top w5.25: MC1.48@4362.2,2005.3 4375,2005.3 4381.87,2012.18 4512.34,2012.18 4790.78,2290.62 4790.78,2501.8 4803.04,2514.06 4839.44,2514.06 4842.52,2510.98 MC5.39@4842.52,2480.31
B64_L16N: MC1.46 MC4.1 | length 629.5
  L1-Top w5.25: MC1.46@4362.2,1980.3 4375,1980.3 4381.87,1973.43 4519.82,1973.43 4796.11,2249.72 4839.44,2249.72 4842.52,2252.79 MC4.1@4842.52,2283.46
B64_L16P: MC1.44 MC4.3 | length 629.5
  L1-Top w5.25: MC1.44@4362.2,1955.3 4375,1955.3 4381.87,1962.18 4524.48,1962.18 4800.77,2238.47 4839.44,2238.47 4842.52,2235.39 MC4.3@4842.52,2204.72
B64_L17N: MC1.42 MC4.5 | length 585
  L1-Top w5.25: MC1.42@4362.2,1930.3 4375,1930.3 4381.87,1923.43 4585.9,1923.43 4754.71,2092.24 4839.44,2092.24 4842.52,2095.31 MC4.5@4842.52,2125.98
B64_L17P: MC1.40 MC4.7 | length 585
  L1-Top w5.25: MC1.40@4362.2,1905.3 4375,1905.3 4381.87,1912.18 4590.56,1912.18 4759.37,2080.99 4839.44,2080.99 4842.52,2077.91 MC4.7@4842.52,2047.24
B64_L18N: MC1.38 MC4.9 | length 540.5
  L1-Top w5.25: MC1.38@4362.2,1880.3 4375,1880.3 4381.87,1873.43 4651.79,1873.43 4713.12,1934.76 4839.44,1934.76 4842.52,1937.83 MC4.9@4842.52,1968.5
B64_L18P: MC1.36 MC4.11 | length 540.5
  L1-Top w5.25: MC1.36@4362.2,1855.3 4375,1855.3 4381.87,1862.18 4656.45,1862.18 4717.78,1923.51 4839.44,1923.51 4842.52,1920.43 MC4.11@4842.52,1889.76
B64_L19N: MC1.57 MC5.30 | length 1225.2
  L1-Top w5.25: v1(4257.87,2130.8) 4259.32,2130.8 4266.7,2123.43 4279.54,2123.43 4286.42,2130.3 MC1.57@4299.21,2130.3
  L4-BOT w5.25: v1(4257.87,2130.8) 4260.95,2130.8 4268.32,2123.43 4424.22,2123.43 4697.41,2396.62 4697.41,2739.07 4758.09,2799.75 4774.55,2799.75 4808.27,2833.48 4880.72,2833.48 MC5.30@4921.26,2874.02
B64_L19P: MC1.55 MC5.32 | length 1225.7
  L1-Top w5.25: v1(4257.87,2104.8) 4259.32,2104.8 4266.7,2112.18 4279.54,2112.18 4286.42,2105.3 MC1.55@4299.21,2105.3
  L4-BOT w5.25: v1(4257.87,2104.8) 4260.95,2104.8 4268.32,2112.18 4428.88,2112.18 4708.66,2391.96 4708.66,2734.41 4762.75,2788.5 4774.49,2788.5 4808.82,2754.18 4880.16,2754.18 MC5.32@4921.26,2795.28
B64_L20N: MC1.53 MC5.34 | length 1232.8
  L1-Top w5.25: v1(4200.79,2080.8) 4203.86,2080.8 4211.24,2073.43 4279.54,2073.43 4286.42,2080.3 MC1.53@4299.21,2080.3
  L4-BOT w5.25: v1(4200.79,2080.8) 4203.86,2080.8 4211.24,2073.43 4423.01,2073.43 4731.91,2382.33 4731.91,2618.9 4755.28,2642.27 4774.55,2642.27 4808.27,2676 4880.72,2676 MC5.34@4921.26,2716.54
B64_L20P: MC1.51 MC5.36 | length 1233.3
  L1-Top w5.25: v1(4200.79,2054.8) 4203.86,2054.8 4211.24,2062.18 4279.54,2062.18 4286.42,2055.3 MC1.51@4299.21,2055.3
  L4-BOT w5.25: v1(4200.79,2054.8) 4203.86,2054.8 4211.24,2062.18 4427.67,2062.18 4743.16,2377.67 4743.16,2614.24 4759.94,2631.02 4774.49,2631.02 4808.82,2596.7 4880.16,2596.7 MC5.36@4921.26,2637.8
B64_L21N: MC1.49 MC5.38 | length 983.2
  L1-Top w5.25: v1(4257.87,2030.8) 4259.32,2030.8 4266.7,2023.43 4279.54,2023.43 4286.42,2030.3 MC1.49@4299.21,2030.3
  L4-BOT w5.25: v1(4257.87,2030.8) 4260.95,2030.8 4268.32,2023.43 4429.23,2023.43 4826.28,2420.48 4863.95,2420.48 4884.42,2440.94 4884.42,2522.21 MC5.38@4921.26,2559.06
B64_L21P: MC1.47 MC5.40 | length 983.2
  L1-Top w5.25: v1(4257.87,2004.8) 4259.32,2004.8 4266.7,2012.18 4279.54,2012.18 4286.42,2005.3 MC1.47@4299.21,2005.3
  L4-BOT w5.25: v1(4257.87,2004.8) 4260.95,2004.8 4268.32,2012.18 4433.89,2012.18 4711.51,2289.8 4734.76,2313.05 cw(c4739.04,2308.77) 4743.32,2313.05 4752.44,2303.93 ccw(c4756.72,2308.21) 4760.99,2303.93 4773.83,2316.76 ccw(c4769.55,2321.04) 4773.83,2325.32 4764.71,2334.44 cw(c4768.98,2338.72) 4764.71,2343 4777.54,2355.83 cw(c4781.82,2351.55) 4786.1,2355.83 4790.1,2351.82 ccw(c4794.38,2356.1) 4798.66,2351.82 4811.49,2364.66 ccw(c4807.21,2368.93) 4811.49,2373.21 4807.49,2377.22 cw(c4811.76,2381.5) 4807.49,2385.78 4824.42,2402.71 4830.94,2409.23 4868.61,2409.23 4895.67,2436.28 4895.67,2454.72 MC5.40@4921.26,2480.31
B64_L22N: MC1.45 MC4.2 | length 956.3
  L1-Top w5.25: v1(4200.79,1980.8) 4203.86,1980.8 4211.24,1973.43 4279.54,1973.43 4286.42,1980.3 MC1.45@4299.21,1980.3
  L4-BOT w5.25: v1(4200.79,1980.8) 4203.86,1980.8 4211.24,1973.43 4500.37,1973.43 4736.14,2209.2 4774.55,2209.2 4808.27,2242.92 4880.72,2242.92 MC4.2@4921.26,2283.46
B64_L22P: MC1.43 MC4.4 | length 956.8
  L1-Top w5.25: v1(4200.79,1954.8) 4203.86,1954.8 4211.24,1962.18 4279.54,1962.18 4286.42,1955.3 MC1.43@4299.21,1955.3
  L4-BOT w5.25: v1(4200.79,1954.8) 4203.86,1954.8 4211.24,1962.18 4505.03,1962.18 4740.8,2197.95 4774.49,2197.95 4808.82,2163.62 4880.16,2163.62 MC4.4@4921.26,2204.72
B64_L23N: MC1.41 MC4.6 | length 797.6
  L1-Top w5.25: v1(4257.87,1930.8) 4259.32,1930.8 4266.7,1923.43 4279.54,1923.43 4286.42,1930.3 MC1.41@4299.21,1930.3
  L4-BOT w5.25: v1(4257.87,1930.8) 4260.95,1930.8 4268.32,1923.43 4612.33,1923.43 4740.62,2051.72 4774.55,2051.72 4808.27,2085.44 4880.72,2085.44 MC4.6@4921.26,2125.98
B64_L23P: MC1.39 MC4.8 | length 798.1
  L1-Top w5.25: v1(4257.87,1904.8) 4259.32,1904.8 4266.7,1912.18 4279.54,1912.18 4286.42,1905.3 MC1.39@4299.21,1905.3
  L4-BOT w5.25: v1(4257.87,1904.8) 4260.95,1904.8 4268.32,1912.18 4616.99,1912.18 4745.28,2040.47 4774.49,2040.47 4808.82,2006.14 4880.16,2006.14 MC4.8@4921.26,2047.24
B64_L24N: MC1.37 MC4.10 | length 867.2
  L1-Top w5.25: v1(4200.79,1880.8) 4203.86,1880.8 4211.24,1873.43 4279.54,1873.43 4286.42,1880.3 MC1.37@4299.21,1880.3
  L4-BOT w5.25: v1(4200.79,1880.8) 4203.86,1880.8 4211.24,1873.43 4681.08,1873.43 4701.89,1894.24 4774.55,1894.24 4808.27,1927.96 4880.72,1927.96 MC4.10@4921.26,1968.5
B64_L24P: MC1.35 MC4.12 | length 867.7
  L1-Top w5.25: v1(4200.79,1854.8) 4203.86,1854.8 4211.24,1862.18 4279.54,1862.18 4286.42,1855.3 MC1.35@4299.21,1855.3
  L4-BOT w5.25: v1(4200.79,1854.8) 4203.86,1854.8 4211.24,1862.18 4685.74,1862.18 4706.55,1882.99 4774.49,1882.99 4808.82,1848.66 4880.16,1848.66 MC4.12@4921.26,1889.76
B64_T1U_N12: MC1.88 MC5.1 | length 1722.1
  L1-Top w7.5: MC1.88@4362.2,2505.3 4411.68,2505.3 4440.92,2534.54 4440.92,3545.96 4793.31,3898.35 4793.31,3966.54 4803.15,3976.38 MC5.1@4842.52,3976.38
B64_T2U_N12: MC1.60 MC5.27 | length 1072.8
  L1-Top w7.5: MC1.60@4362.2,2155.3 4449.26,2155.3 4677.14,2383.18 4677.14,2830.68 4799.21,2952.76 MC5.27@4842.52,2952.76
B64_T3U_N12: MC1.59 MC5.28 | length 1365.9
  L1-Top w7.5: v1(4211.24,2155.3) 4241.05,2155.3 4245.58,2159.84 4268.09,2159.84 4272.62,2155.3 MC1.59@4299.21,2155.3
  L4-BOT w7.5: v1(4211.24,2155.3) 4241.7,2155.3 4246.72,2160.33 4267.82,2160.33 4272.84,2155.3 4405.68,2155.3 4672.42,2422.04 4672.42,2814.15 4771.65,2913.39 4881.89,2913.39 MC5.28@4921.26,2952.76
B84_L1N: MC1.12 MC4.33 | length 872.7
  L1-Top w5.25: MC1.12@4362.2,1555.3 4375,1555.3 4381.87,1548.43 4442.59,1548.43 4712.94,1278.08 4712.94,1062.65 4785.71,989.88 4839.44,989.88 4842.52,992.95 MC4.33@4842.52,1023.62
B84_L1P: MC1.10 MC4.35 | length 872.7
  L1-Top w5.25: MC1.10@4362.2,1530.3 4375,1530.3 4381.87,1537.18 4437.93,1537.18 4701.69,1273.42 4701.69,1057.99 4781.05,978.63 4839.44,978.63 4842.52,975.55 MC4.35@4842.52,944.88
B84_L2N: MC1.16 MC4.29 | length 767.2
  L1-Top w5.25: MC1.16@4362.2,1605.3 4375,1605.3 4381.87,1598.43 4449.64,1598.43 4760.18,1287.89 4760.18,1176.51 4789.34,1147.36 4839.44,1147.36 4842.52,1150.43 MC4.29@4842.52,1181.1
B84_L2P: MC1.14 MC4.31 | length 767.2
  L1-Top w5.25: MC1.14@4362.2,1580.3 4375,1580.3 4381.87,1587.18 4444.98,1587.18 4748.93,1283.23 4748.93,1171.85 4784.68,1136.11 4839.44,1136.11 4842.52,1133.03 MC4.31@4842.52,1102.36
B84_L3N: MC1.20 MC4.25 | length 657.4
  L1-Top w5.25: MC1.20@4362.2,1655.3 4375,1655.3 4381.87,1648.43 4460.3,1648.43 4803.89,1304.84 4839.44,1304.84 4842.52,1307.91 MC4.25@4842.52,1338.58
B84_L3P: MC1.18 MC4.27 | length 657.4
  L1-Top w5.25: MC1.18@4362.2,1630.3 4375,1630.3 4381.87,1637.18 4455.64,1637.18 4799.23,1293.59 4839.44,1293.59 4842.52,1290.51 MC4.27@4842.52,1259.84
B84_L4N: MC1.24 MC4.21 | length 612.9
  L1-Top w5.25: MC1.24@4362.2,1705.3 4375,1705.3 4381.87,1698.43 4526.23,1698.43 4762.34,1462.32 4839.44,1462.32 4842.52,1465.39 MC4.21@4842.52,1496.06
B84_L4P: MC1.22 MC4.23 | length 612.9
  L1-Top w5.25: MC1.22@4362.2,1680.3 4375,1680.3 4381.87,1687.18 4521.57,1687.18 4757.68,1451.07 4839.44,1451.07 4842.52,1447.99 MC4.23@4842.52,1417.32
B84_L5N_HDGC: MC1.28 MC4.17 | length 568.4
  L1-Top w5.25: MC1.28@4362.2,1755.3 4375,1755.3 4381.87,1748.43 4597.59,1748.43 4726.23,1619.8 4839.44,1619.8 4842.52,1622.87 MC4.17@4842.52,1653.54
B84_L5P_HDGC: MC1.26 MC4.19 | length 568.4
  L1-Top w5.25: MC1.26@4362.2,1730.3 4375,1730.3 4381.87,1737.18 4592.93,1737.18 4721.57,1608.55 4839.44,1608.55 4842.52,1605.47 MC4.19@4842.52,1574.8
B84_L6N_HDGC: MC1.32 MC4.13 | length 523.9
  L1-Top w5.25: MC1.32@4362.2,1805.3 4375,1805.3 4381.87,1798.43 4673.94,1798.43 4695.09,1777.28 4839.44,1777.28 4842.52,1780.35 MC4.13@4842.52,1811.02
B84_L6P_HDGC: MC1.30 MC4.15 | length 523.9
  L1-Top w5.25: MC1.30@4362.2,1780.3 4375,1780.3 4381.87,1787.18 4669.28,1787.18 4690.43,1766.03 4839.44,1766.03 4842.52,1762.95 MC4.15@4842.52,1732.28
B84_L7N_HDGC: MC1.11 MC4.34 | length 1184.7
  L1-Top w5.25: v1(4200.79,1555.8) 4203.86,1555.8 4211.24,1548.43 4279.54,1548.43 4286.42,1555.3 MC1.11@4299.21,1555.3
  L4-BOT w5.25: v1(4200.79,1555.8) 4203.86,1555.8 4211.24,1548.43 4294.63,1548.43 4323.26,1519.8 4323.26,1479.02 4395.03,1407.25 4395.03,1314.99 4760.66,949.36 4774.55,949.36 4808.27,983.08 4880.72,983.08 MC4.34@4921.26,1023.62
B84_L7P_HDGC: MC1.9 MC4.36 | length 1185.2
  L1-Top w5.25: v1(4200.79,1529.8) 4203.86,1529.8 4211.24,1537.18 4279.54,1537.18 4286.42,1530.3 MC1.9@4299.21,1530.3
  L4-BOT w5.25: v1(4200.79,1529.8) 4203.86,1529.8 4211.24,1537.18 4289.97,1537.18 4312.01,1515.14 4312.01,1474.36 4383.78,1402.59 4383.78,1310.33 4756,938.11 4774.49,938.11 4808.82,903.78 4880.16,903.78 MC4.36@4921.26,944.88
B84_L8N_HDGC: MC1.15 MC4.30 | length 1015.5
  L1-Top w5.25: v1(4257.87,1605.8) 4259.32,1605.8 4266.7,1598.43 4279.54,1598.43 4286.42,1605.3 MC1.15@4299.21,1605.3
  L4-BOT w5.25: v1(4257.87,1605.8) 4260.95,1605.8 4268.32,1598.43 4378.95,1598.43 4479.75,1497.63 4479.75,1382.57 4755.49,1106.84 4774.55,1106.84 4808.27,1140.56 4880.72,1140.56 MC4.30@4921.26,1181.1
B84_L8P_HDGC: MC1.13 MC4.32 | length 1015.9
  L1-Top w5.25: v1(4257.87,1579.8) 4259.32,1579.8 4266.7,1587.18 4279.54,1587.18 4286.42,1580.3 MC1.13@4299.21,1580.3
  L4-BOT w5.25: v1(4257.87,1579.8) 4260.95,1579.8 4268.32,1587.18 4374.29,1587.18 4468.5,1492.97 4468.5,1377.91 4750.83,1095.59 4774.49,1095.59 4808.82,1061.26 4880.16,1061.26 MC4.32@4921.26,1102.36
B84_L9N: MC1.19 MC4.26 | length 1045.1
  L1-Top w5.25: v1(4200.79,1655.8) 4203.86,1655.8 4211.24,1648.43 4279.54,1648.43 4286.42,1655.3 MC1.19@4299.21,1655.3
  L4-BOT w5.25: v1(4200.79,1655.8) 4203.86,1655.8 4211.24,1648.43 4418.78,1648.43 4571.36,1495.84 4571.36,1449.16 4583.11,1437.41 4756.21,1264.32 4774.55,1264.32 4808.27,1298.04 4880.72,1298.04 MC4.26@4921.26,1338.58
B84_L9P: MC1.17 MC4.28 | length 1045.5
  L1-Top w5.25: v1(4200.79,1629.8) 4203.86,1629.8 4211.24,1637.18 4279.54,1637.18 4286.42,1630.3 MC1.17@4299.21,1630.3
  L4-BOT w5.25: v1(4200.79,1629.8) 4203.86,1629.8 4211.24,1637.18 4414.12,1637.18 4560.11,1491.18 4560.11,1444.5 4571.86,1432.75 4751.55,1253.07 4774.49,1253.07 4808.82,1218.74 4880.16,1218.74 MC4.28@4921.26,1259.84
B84_L10N: MC1.23 MC4.22 | length 859
  L1-Top w5.25: v1(4257.87,1705.8) 4259.32,1705.8 4266.7,1698.43 4279.54,1698.43 4286.42,1705.3 MC1.23@4299.21,1705.3
  L4-BOT w5.25: v1(4257.87,1705.8) 4260.95,1705.8 4268.32,1698.43 4481.54,1698.43 4648.51,1531.46 4758.17,1421.8 4774.55,1421.8 4808.27,1455.52 4880.72,1455.52 MC4.22@4921.26,1496.06
B84_L10P: MC1.21 MC4.24 | length 859.5
  L1-Top w5.25: v1(4257.87,1679.8) 4259.32,1679.8 4266.7,1687.18 4279.54,1687.18 4286.42,1680.3 MC1.21@4299.21,1680.3
  L4-BOT w5.25: v1(4257.87,1679.8) 4260.95,1679.8 4268.32,1687.18 4476.88,1687.18 4637.26,1526.8 4753.51,1410.55 4774.49,1410.55 4808.82,1376.22 4880.16,1376.22 MC4.24@4921.26,1417.32
B84_L11N: MC1.27 MC4.18 | length 928.7
  L1-Top w5.25: v1(4200.79,1755.8) 4203.86,1755.8 4211.24,1748.43 4279.54,1748.43 4286.42,1755.3 MC1.27@4299.21,1755.3
  L4-BOT w5.25: v1(4200.79,1755.8) 4203.86,1755.8 4211.24,1748.43 4572.48,1748.43 4741.64,1579.28 4774.55,1579.28 4808.27,1613 4880.72,1613 MC4.18@4921.26,1653.54
B84_L11P: MC1.25 MC4.20 | length 929.2
  L1-Top w5.25: v1(4200.79,1729.8) 4203.86,1729.8 4211.24,1737.18 4279.54,1737.18 4286.42,1730.3 MC1.25@4299.21,1730.3
  L4-BOT w5.25: v1(4200.79,1729.8) 4203.86,1729.8 4211.24,1737.18 4567.83,1737.18 4736.98,1568.03 4774.49,1568.03 4808.82,1533.7 4880.16,1533.7 MC4.20@4921.26,1574.8
B84_L12N: MC1.31 MC4.14 | length 770
  L1-Top w5.25: v1(4257.87,1805.8) 4259.32,1805.8 4266.7,1798.43 4279.54,1798.43 4286.42,1805.3 MC1.31@4299.21,1805.3
  L4-BOT w5.25: v1(4257.87,1805.8) 4260.95,1805.8 4268.32,1798.43 4685.98,1798.43 4747.65,1736.76 4774.55,1736.76 4808.27,1770.48 4880.72,1770.48 MC4.14@4921.26,1811.02
B84_L12P: MC1.29 MC4.16 | length 770.5
  L1-Top w5.25: v1(4257.87,1779.8) 4259.32,1779.8 4266.7,1787.18 4279.54,1787.18 4286.42,1780.3 MC1.29@4299.21,1780.3
  L4-BOT w5.25: v1(4257.87,1779.8) 4260.95,1779.8 4268.32,1787.18 4681.32,1787.18 4742.99,1725.51 4774.49,1725.51 4808.82,1691.18 4880.16,1691.18 MC4.16@4921.26,1732.28
B85_L6N_HDGC: MC2.33 MC6.40 | length 3148.8
  L1-Top w7.5: v1(2393.59,1715.55) MC2.33@2452.76,1715.55
  L4-BOT w7.5: MC6.40@2132.08,3819.29 2171.4,3779.97 2237.57,3779.97 3022.62,2994.92 3022.62,1802.15 2936.02,1715.55 v1(2393.59,1715.55)
B85_L7N_HDGC: MC2.24 MC6.37 | length 2920.2
  L1-Top w5.25: MC6.37@2210.82,3740.55 2210.82,3771.22 2213.89,3774.3 2262.41,3774.3 2994.4,3042.31 2996.26,3040.45 3017.65,3019.06 cw(c3013.37,3014.78) 3017.65,3010.5 3009.35,3002.21 ccw(c3013.63,2997.93) 3009.35,2993.65 3022.18,2980.82 ccw(c3026.46,2985.09) 3030.74,2980.82 3039.04,2989.11 cw(c3043.31,2984.84) 3047.59,2989.11 3063.47,2973.24 3065.32,2971.38 3069.98,2966.72 3069.98,2066.44 2587.22,1583.68 2535.42,1583.68 2528.54,1590.55 MC2.24@2515.75,1590.55
B85_L7P_HDGC: MC2.22 MC6.39 | length 2920.2
  L1-Top w5.25: MC6.39@2210.82,3819.29 2210.82,3788.62 2213.89,3785.55 2267.07,3785.55 3081.23,2971.38 3081.23,2061.78 2591.88,1572.43 2535.42,1572.43 2528.54,1565.55 MC2.22@2515.75,1565.55
B85_L8N_HDGC: MC2.28 MC6.33 | length 2681
  L1-Top w5.25: MC6.33@2210.82,3583.07 2210.82,3613.74 2213.89,3616.82 2269.49,3616.82 2951.63,2934.68 2953.49,2932.82 2974.88,2911.43 cw(c2970.6,2907.15) 2974.88,2902.87 2966.58,2894.58 ccw(c2970.86,2890.3) 2966.58,2886.02 2979.42,2873.19 ccw(c2983.69,2877.47) 2987.97,2873.19 2996.27,2881.48 cw(c3000.55,2877.21) 3004.82,2881.48 3019.28,2867.02 3021.14,2865.17 3025.8,2860.51 3025.8,2071.04 2588.43,1633.68 2535.42,1633.68 2528.54,1640.55 MC2.28@2515.75,1640.55
B85_L8P_HDGC: MC2.26 MC6.35 | length 2681
  L1-Top w5.25: MC6.35@2210.82,3661.81 2210.82,3631.14 2213.89,3628.07 2274.15,3628.07 3037.05,2865.17 3037.05,2066.38 2593.09,1622.43 2535.42,1622.43 2528.54,1615.55 MC2.26@2515.75,1615.55
B85_L9N: MC2.32 MC6.29 | length 2445.8
  L1-Top w5.25: MC6.29@2210.82,3425.59 2210.82,3456.26 2213.89,3459.34 2289.75,3459.34 2899.81,2849.27 2901.67,2847.42 2923.06,2826.03 cw(c2918.78,2821.75) 2923.06,2817.47 2914.76,2809.18 ccw(c2919.04,2804.9) 2914.76,2800.62 2927.59,2787.79 ccw(c2931.87,2792.06) 2936.15,2787.78 2944.45,2796.08 cw(c2948.72,2791.8) 2953,2796.08 2973.78,2775.31 2975.63,2773.45 2977.19,2771.89 2977.19,2071.23 2589.64,1683.68 2535.42,1683.68 2528.54,1690.55 MC2.32@2515.75,1690.55
B85_L9P: MC2.30 MC6.31 | length 2445.8
  L1-Top w5.25: MC6.31@2210.82,3504.33 2210.82,3473.66 2213.89,3470.59 2294.41,3470.59 2988.44,2776.55 2988.44,2066.57 2594.3,1672.43 2535.42,1672.43 2528.54,1665.55 MC2.30@2515.75,1665.55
